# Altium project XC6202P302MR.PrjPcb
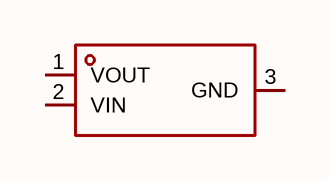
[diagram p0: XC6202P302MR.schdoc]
1 sheet, 1 parts. Net scope: global (net labels, ports and power ports of the same name join across sheets).

## Sheet XC6202P302MR.schdoc
size 127 x 101 mm

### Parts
U?  xc6202p302mr  [SOT-23-3_L2.9-W1.6-P1.90-LS2.8-BR]  (value not drawn)

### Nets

Not connected (* = marked no-connect by the designer): U? 1(VOUT) 2(VIN) 3(GND)

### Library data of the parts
U? = xc6202p302mr: 输出极性:正极;工作电压:15V;输出电压:3V;输出电流:150mA;电源纹波抑制比(PSRR):40dB@(1kHz);输出类型:固定;; Manufacturer: TECH PUBLIC(台舟); AddInBom: yes; ModelId: 89cb27a44ab2466697082bb9fd73a7d0; ModelName: SOT-23-3L_L2.9-W1.6-H1.1-LS2.8-P0.95; ModelTransform: 114.173,110.236,0,90,0,0,0,0,0; Output Configuration: 正极; Voltage - Supply: 15V; Output Voltage: 3V; Output Current: 150mA; Output Type: 固定; Number of Outputs: 1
